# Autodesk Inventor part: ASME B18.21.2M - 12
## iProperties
Created: 2006-02
Part Number: ASME B18.21.2M - 12
Material: Steel, Mild
Description: Heavy Helical Spring Lock Washers
Document SubType Name: Modeling
Standard: ASME B18.21.2M
Designer: Administrator
Standards Organization: ANSI
Language: en-US
Categories: <MemberInstance><Categories><Category DisplayName="Fasteners" InternalName="e4da775c-781d-43d5-af7c-5136215cf5a6" Mnemonic="FSTN"><Category DisplayName="Washers
Density: 7.86 g/cm^3
Author: Administrator
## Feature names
1. Extrusion1
2. Hole1
3. Extrusion2
